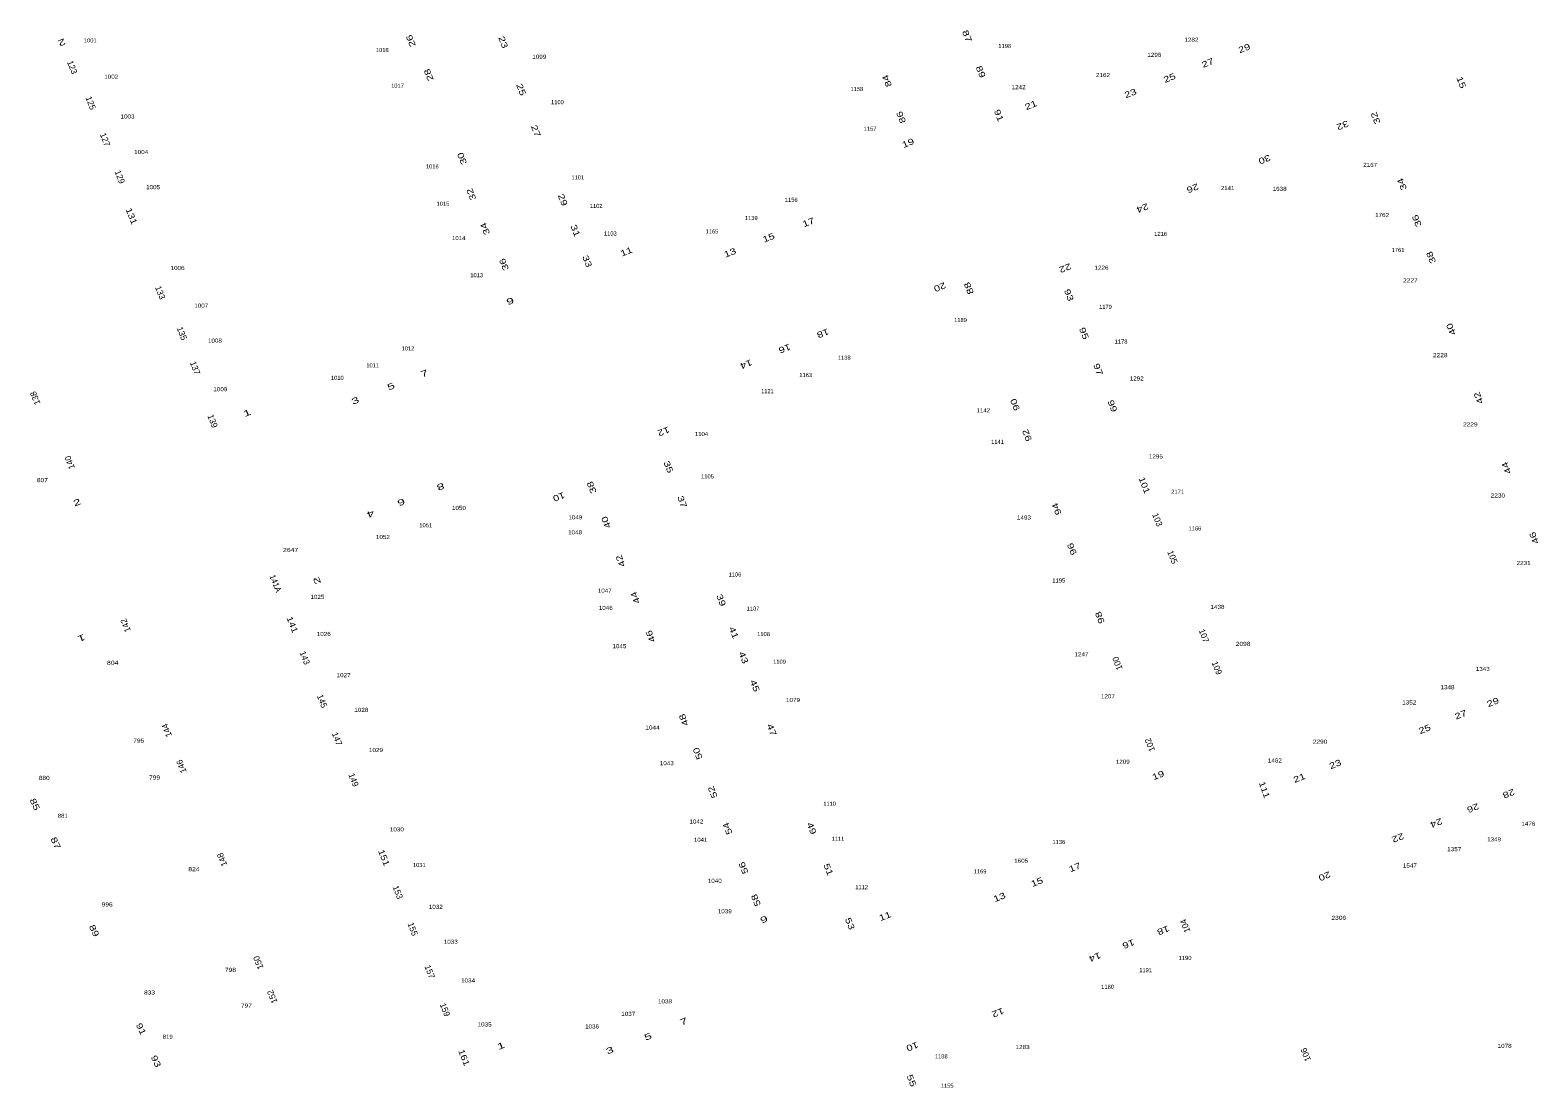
# Model space of a CAD drawing. Extents: x -828673 to -815583, y -1077737 to -1063807.
# Drawn here: x -821441.6 to -821072.8, y -1072104.4 to -1071845.8 of the extents above; entities that cross this region are included whole.
import ezdxf
from ezdxf.enums import TextEntityAlignment as Align

# ---------------------------------------------------------------- set-up
doc = ezdxf.new("R2010")
doc.units = 0
doc.header["$LTSCALE"] = 0.4
doc.layers.add('1', color=7, linetype='Continuous')
doc.layers.add('2', color=7, linetype='Continuous')

msp = doc.modelspace()

# ---------------------------------------------------------------- texts
at = {"layer": '1'}
for s, width, p in [('1001', 1.05, (-821426.855, -1071848.838)), ('1018', 1.05, (-821355.448, -1071851.177)), ('1198', 1.05, (-821203.208, -1071850.196)), ('1282', 1.15, (-821157.545, -1071848.648)), ('1099', 1.15, (-821317.042, -1071852.844)), ('1296', 1.15, (-821166.627, -1071852.363)), ('1002', 1.15, (-821421.722, -1071857.701)), ('2162', 1.15, (-821179.183, -1071857.314)), ('1017', 1.05, (-821351.728, -1071859.925)), ('1158', 1.05, (-821239.376, -1071860.714)), ('1242', 1.15, (-821199.808, -1071860.268)), ('1100', 1.05, (-821312.602, -1071863.939)), ('1003', 1.15, (-821417.748, -1071867.433)), ('1157', 1.05, (-821236.132, -1071870.425)), ('1004', 1.15, (-821414.395, -1071876.13)), ('1016', 1.05, (-821343.2, -1071879.639)), ('2167', 1.15, (-821113.836, -1071879.273)), ('1005', 1.15, (-821411.5, -1071884.718)), ('1156', 1.05, (-821255.43, -1071887.812)), ('2141', 1.1, (-821148.692, -1071884.94)), ('1638', 1.15, (-821135.975, -1071885.124)), ('1015', 1.05, (-821340.598, -1071888.764)), ('1102', 1.05, (-821303.131, -1071889.296)), ('1762', 1.15, (-821110.933, -1071891.535)), ('1165', 1.05, (-821274.809, -1071895.536)), ('1139', 1.05, (-821265.198, -1071892.245)), ('1014', 1.1, (-821336.749, -1071897.171)), ('1103', 1.05, (-821299.671, -1071896.049)), ('1216', 1.05, (-821165.095, -1071896.142)), ('1761', 1.05, (-821107.016, -1071900.063)), ('1006', 1.15, (-821405.508, -1071904.477)), ('1013', 1.05, (-821332.361, -1071906.239)), ('1226', 1.15, (-821179.548, -1071904.408)), ('2227', 1.2, (-821103.984, -1071907.495)), ('1007', 1.15, (-821399.713, -1071913.671)), ('1179', 1.05, (-821178.581, -1071913.983)), ('1189', 1.05, (-821214.032, -1071917.207)), ('1008', 1.15, (-821396.369, -1071922.226)), ('1012', 1.05, (-821349.164, -1071924.144)), ('1178', 1.05, (-821174.757, -1071922.465)), ('1138', 1.05, (-821242.466, -1071926.4)), ('2228', 1.2, (-821096.704, -1071925.796)), ('1010', 1.05, (-821366.44, -1071931.337)), ('1163', 1.05, (-821251.869, -1071930.649)), ('1292', 1.15, (-821170.932, -1071931.5)), ('1009', 1.15, (-821395.044, -1071934.112)), ('1142', 1.1, (-821208.442, -1071939.285)), ('2229', 1.2, (-821089.341, -1071942.722)), ('1104', 1.1, (-821277.375, -1071945.06)), ('1295', 1.15, (-821166.236, -1071950.549)), ('807', 1.2, (-821438.554, -1071956.347)), ('1105', 1.05, (-821275.916, -1071955.437)), ('2171', 1.05, (-821160.938, -1071959.169)), ('2230', 1.2, (-821082.614, -1071960.101)), ('1050', 1.15, (-821336.695, -1071963.133)), ('1049', 1.15, (-821308.221, -1071965.424)), ('1493', 1.15, (-821198.51, -1071965.495)), ('1051', 1.05, (-821344.808, -1071967.378)), ('1048', 1.15, (-821308.299, -1071969.09)), ('1166', 1.05, (-821156.699, -1071968.158)), ('1052', 1.15, (-821355.291, -1071970.25)), ('2647', 1.25, (-821377.862, -1071973.433)), ('2231', 1.15, (-821076.307, -1071976.618)), ('1106', 1.05, (-821269.183, -1071979.421)), ('1047', 1.15, (-821301.031, -1071983.375)), ('1195', 1.05, (-821189.997, -1071980.891)), ('1025', 1.15, (-821371.31, -1071984.893)), ('1046', 1.15, (-821300.782, -1071987.579)), ('1107', 1.05, (-821264.765, -1071987.747)), ('1438', 1.15, (-821151.179, -1071987.34)), ('1026', 1.15, (-821369.749, -1071993.951)), ('1108', 1.05, (-821262.201, -1071993.981)), ('1045', 1.15, (-821297.454, -1071996.943)), ('1247', 1.15, (-821184.436, -1071998.922)), ('2098', 1.2, (-821144.913, -1071996.375)), ('804', 1.25, (-821421.362, -1072001.001)), ('1109', 1.05, (-821258.297, -1072000.728)), ('1343', 1.15, (-821086.3, -1072002.502)), ('1027', 1.15, (-821364.891, -1072004.029)), ('1207', 1.15, (-821177.976, -1072009.186)), ('1348', 1.15, (-821094.916, -1072006.973)), ('1028', 1.15, (-821360.564, -1072012.519)), ('1079', 1.15, (-821254.991, -1072010.09)), ('1352', 1.15, (-821104.269, -1072010.707)), ('1044', 1.2, (-821289.353, -1072016.842)), ('795', 1.2, (-821415.002, -1072020.029)), ('2290', 1.2, (-821126.092, -1072020.284)), ('1029', 1.15, (-821356.986, -1072022.342)), ('1043', 1.15, (-821285.858, -1072025.541)), ('1209', 1.15, (-821174.348, -1072025.205)), ('1462', 1.15, (-821137.15, -1072024.894)), ('880', 1.2, (-821438.114, -1072029.147)), ('799', 1.2, (-821411.121, -1072029.06)), ('881', 1.1, (-821433.579, -1072038.397)), ('1030', 1.15, (-821351.878, -1072041.738)), ('1042', 1.15, (-821278.619, -1072039.816)), ('1476', 1.15, (-821075.162, -1072040.36)), ('1041', 1.1, (-821277.584, -1072044.274)), ('1111', 0.9, (-821244, -1072044.024)), ('1136', 1.05, (-821189.994, -1072044.815)), ('1357', 1.15, (-821093.279, -1072046.576)), ('1349', 1.15, (-821083.539, -1072044.17)), ('1031', 1.05, (-821346.387, -1072050.436)), ('1605', 1.15, (-821199.183, -1072049.392)), ('824', 1.25, (-821401.491, -1072051.458)), ('1169', 1.05, (-821209.239, -1072051.996)), ('1547', 1.15, (-821104.125, -1072050.57)), ('1040', 1.15, (-821274.131, -1072054.305)), ('996', 1.2, (-821422.728, -1072060.096)), ('1032', 1.15, (-821342.351, -1072060.675)), ('1039', 1.15, (-821271.677, -1072061.755)), ('2306', 1.2, (-821121.52, -1072063.362)), ('1033', 1.15, (-821338.691, -1072069.207)), ('798', 1.2, (-821392.557, -1072076.079)), ('1190', 1.05, (-821159.105, -1072073.164)), ('1034', 1.15, (-821334.466, -1072078.662)), ('833', 1.2, (-821412.355, -1072081.62)), ('1180', 1.05, (-821178.056, -1072080.233)), ('797', 1.2, (-821388.676, -1072084.848)), ('1037', 1.15, (-821295.281, -1072086.847)), ('1038', 1.15, (-821286.3, -1072083.77)), ('1035', 1.15, (-821330.406, -1072089.432)), ('1036', 1.15, (-821304.139, -1072089.925)), ('819', 1.1, (-821407.907, -1072092.44)), ('1078', 1.15, (-821080.947, -1072094.671)), ('1188', 1.05, (-821218.736, -1072097.216)), ('1283', 1.15, (-821198.834, -1072094.948)), ('1155', 1.05, (-821217.284, -1072104.417))]:
    msp.add_text(s, height=1, dxfattribs=dict(at, width=width)).set_placement(p, align=Align.CENTER)
for s, p in [('1101', (-821307.609, -1071882.334)), ('1011', (-821357.789, -1071928.273)), ('1121', (-821261.254, -1071934.595)), ('1141', (-821204.978, -1071946.991)), ('1110', (-821246.042, -1072035.47)), ('1112', (-821238.203, -1072055.86)), ('1191', (-821168.746, -1072076.17))]:
    msp.add_text(s, height=1, dxfattribs=at).set_placement(p, align=Align.CENTER)
at = {"layer": '2'}
for s, rotation, width, p in [('87', 291.612, 1.35, (-821213.1119, -1071847.5658)), ('2', 201.854, 1.65, (-821434.0593, -1071848.1341)), ('26', 111.307, 1.35, (-821347.7676, -1071848.1805)), ('23', 291.4, 1.35, (-821326.5503, -1071849.0453)), ('29', 21.878, 1.35, (-821144.3525, -1071850.9592)), ('27', 21.908, 1.35, (-821153.2858, -1071854.5225)), ('28', 111.366, 1.35, (-821343.3849, -1071856.5152)), ('84', 111.699, 1.35, (-821231.3212, -1071857.9743)), ('89', 291.69, 1.35, (-821209.77, -1071856.2768)), ('25', 21.865, 1.35, (-821162.6348, -1071858.1937)), ('15', 291.488, 1.35, (-821092.251, -1071858.8678)), ('25', 291.631, 1.35, (-821322.1484, -1071860.6285)), ('23', 21.315, 1.35, (-821172.2096, -1071861.9563)), ('21', 21.878, 1.35, (-821196.5365, -1071864.8572)), ('86', 111.334, 1.35, (-821227.861, -1071866.8724)), ('91', 291.552, 1.35, (-821205.3375, -1071866.943)), ('32', 201.845, 1.35, (-821120.8469, -1071868.415)), ('32', 111.531, 1.35, (-821111.8282, -1071867.0482)), ('27', 291.657, 1.35, (-821318.5638, -1071870.7392)), ('19', 21.763, 1.35, (-821226.5776, -1071874.1151)), ('30', 111.53, 1.35, (-821335.2402, -1071876.9522)), ('30', 201.754, 1.35, (-821139.9455, -1071876.7557)), ('26', 201.801, 1.35, (-821157.524, -1071883.7998)), ('34', 111.633, 1.35, (-821105.3786, -1071883.2295)), ('32', 111.778, 1.35, (-821332.9712, -1071885.7028)), ('29', 291.829, 1.35, (-821311.9884, -1071887.5971)), ('131', 291.645, 1.25, (-821417.4698, -1071891.5749)), ('24', 201.251, 1.35, (-821169.7807, -1071888.638)), ('36', 111.567, 1.35, (-821101.7389, -1071892.1722)), ('34', 111.848, 1.35, (-821329.6191, -1071894.1101)), ('31', 291.488, 1.35, (-821308.899, -1071895.1208)), ('17', 21.485, 1.35, (-821250.9452, -1071893.5011)), ('15', 21.571, 1.35, (-821260.6842, -1071897.263)), ('36', 111.506, 1.35, (-821324.9804, -1071902.8485)), ('33', 291.674, 1.35, (-821306.0084, -1071902.616)), ('11', 21.48, 1.35, (-821295.4761, -1071900.6742)), ('13', 21.501, 1.35, (-821270.1244, -1071900.9377)), ('38', 111.807, 1.35, (-821098.2459, -1071901.1261)), ('22', 201.151, 1.35, (-821188.7014, -1071903.3115)), ('20', 201.294, 1.35, (-821219.3451, -1071907.963)), ('88', 112.213, 1.35, (-821211.3021, -1071908.6645)), ('93', 291.259, 1.35, (-821188.2008, -1071910.8476)), ('9', 19.822, 1.65, (-821323.9123, -1071912.7973)), ('18', 201.492, 1.35, (-821247.9327, -1071919.2571)), ('95', 291.746, 1.35, (-821184.5125, -1071920.2386)), ('40', 112.82, 1.35, (-821093.3572, -1071918.6659)), ('16', 201.364, 1.35, (-821257.2968, -1071922.9929)), ('14', 201.737, 1.35, (-821266.7217, -1071926.8243)), ('97', 291.522, 1.35, (-821181.0582, -1071929.0414)), ('7', 20.452, 1.65, (-821344.8966, -1071930.4492)), ('5', 21.756, 1.65, (-821353.0265, -1071933.6146)), ('42', 111.621, 1.35, (-821086.6333, -1071935.4983)), ('1', 22.65, 1.65, (-821388.2288, -1071940.0956)), ('3', 22.629, 1.65, (-821361.7636, -1071937.0868)), ('90', 111.497, 1.35, (-821199.9882, -1071937.1283)), ('99', 291.476, 1.35, (-821177.5553, -1071937.9869)), ('12', 201.588, 1.35, (-821286.9051, -1071943.2446)), ('92', 111.524, 1.35, (-821197.0688, -1071944.6247)), ('35', 291.718, 1.35, (-821286.1342, -1071952.88)), ('44', 111.702, 1.35, (-821079.8152, -1071952.6023)), ('8', 201.233, 1.65, (-821341.4389, -1071956.7601)), ('38', 111.603, 1.35, (-821303.5499, -1071957.3571)), ('101', 291.411, 1.25, (-821169.7398, -1071957.3527)), ('2', 21.486, 1.65, (-821429.8252, -1071961.9808)), ('6', 201.219, 1.65, (-821351.0891, -1071960.547)), ('10', 201.497, 1.35, (-821312.5057, -1071959.2522)), ('37', 291.416, 1.35, (-821282.7837, -1071961.4026)), ('4', 201.216, 1.65, (-821358.5771, -1071963.4189)), ('40', 111.642, 1.35, (-821300.0048, -1071965.9116)), ('94', 111.664, 1.35, (-821189.8193, -1071962.6299)), ('96', 111.728, 1.35, (-821186.0791, -1071972.4221)), ('46', 111.633, 1.35, (-821073.0486, -1071969.7175)), ('42', 111.498, 1.35, (-821296.4753, -1071975.3294)), ('141A', 292.085, 0.95, (-821382.2293, -1071981.382)), ('2', 111.686, 1.65, (-821370.7083, -1071980.1451)), ('44', 111.44, 1.35, (-821292.8559, -1071984.3196)), ('39', 291.269, 1.35, (-821273.2515, -1071985.4704)), ('141', 292.087, 1.25, (-821378.1256, -1071991.4505)), ('98', 111.548, 1.35, (-821179.2544, -1071989.191)), ('1', 201.51, 1.65, (-821429.2535, -1071993.7545)), ('46', 111.801, 1.35, (-821289.1138, -1071993.768)), ('41', 291.801, 1.35, (-821270.1652, -1071993.416)), ('43', 291.55, 1.35, (-821267.7775, -1071999.494)), ('45', 291.86, 1.35, (-821265.0156, -1072006.3957)), ('27', 21.444, 1.35, (-821091.4282, -1072013.8772)), ('29', 21.439, 1.35, (-821083.5496, -1072010.8351)), ('48', 111.657, 1.35, (-821281.0112, -1072014.2088)), ('47', 291.439, 1.35, (-821260.8821, -1072017.1784)), ('25', 21.827, 1.35, (-821100.2289, -1072017.4244)), ('50', 111.919, 1.35, (-821277.6007, -1072022.407)), ('19', 21.422, 1.35, (-821165.4094, -1072028.7175)), ('23', 22.019, 1.35, (-821122.0987, -1072025.9877)), ('52', 111.78, 1.35, (-821273.9403, -1072031.8558)), ('111', 289.354, 1.25, (-821140.4079, -1072031.805)), ('21', 21.267, 1.35, (-821130.8915, -1072029.3566)), ('85', 295.286, 1.35, (-821441.0875, -1072035.4276)), ('28', 201.517, 1.35, (-821080.2334, -1072031.8017)), ('24', 201.589, 1.35, (-821097.95, -1072038.9806)), ('26', 201.578, 1.35, (-821088.9707, -1072035.3321)), ('54', 111.759, 1.35, (-821270.3256, -1072040.766)), ('49', 291.516, 1.35, (-821251.1453, -1072041.2544)), ('22', 201.488, 1.35, (-821107.3138, -1072042.613)), ('87', 295.396, 1.35, (-821435.9839, -1072044.8943)), ('151', 291.409, 1.25, (-821355.7269, -1072048.4367)), ('56', 111.812, 1.35, (-821266.414, -1072050.3802)), ('17', 21.516, 1.35, (-821185.7886, -1072051.2073)), ('51', 291.493, 1.35, (-821247.0289, -1072051.3157)), ('15', 21.438, 1.35, (-821195.0556, -1072054.7982)), ('20', 202.416, 1.35, (-821125.269, -1072052.0003)), ('13', 21.601, 1.35, (-821204.2451, -1072058.5051)), ('58', 111.727, 1.35, (-821263.377, -1072058.2871)), ('9', 21.959, 1.65, (-821261.8185, -1072063.9594)), ('53', 291.815, 1.35, (-821241.7649, -1072064.5648)), ('11', 21.196, 1.35, (-821232.2227, -1072063.1512)), ('89', 295.364, 1.35, (-821426.5737, -1072066.3337)), ('18', 201.598, 1.35, (-821164.7209, -1072065.2358)), ('14', 202.024, 1.35, (-821181.4262, -1072071.7794)), ('16', 201.47, 1.35, (-821173.2055, -1072068.5704)), ('12', 201.991, 1.35, (-821205.1422, -1072085.3384)), ('91', 295.482, 1.35, (-821415.0876, -1072090.3548)), ('7', 21.684, 1.65, (-821281.4561, -1072088.8977)), ('1', 21.404, 1.65, (-821326.1487, -1072094.8501)), ('5', 21.05, 1.65, (-821290.1899, -1072092.5956)), ('10', 201.882, 1.35, (-821226.0685, -1072093.6489)), ('93', 295.125, 1.35, (-821411.4486, -1072098.2401)), ('161', 291.58, 1.25, (-821336.137, -1072097.2926)), ('3', 21.374, 1.65, (-821299.5348, -1072095.9577)), ('55', 291.564, 1.35, (-821226.6902, -1072102.9278))]:
    msp.add_text(s, height=1.5, rotation=rotation, dxfattribs=dict(at, width=width)).set_placement(p, align=Align.CENTER)
for s, rotation, p in [('123', 291.843, (-821431.9471, -1071855.174)), ('125', 291.419, (-821427.4347, -1071863.9131)), ('127', 291.565, (-821423.9159, -1071872.8578)), ('129', 291.534, (-821420.3175, -1071881.9857)), ('133', 291.409, (-821410.4337, -1071910.2747)), ('135', 291.577, (-821405.1343, -1071920.2557)), ('137', 291.655, (-821401.9059, -1071928.7042)), ('138', 111.306, (-821439.6283, -1071935.5285)), ('139', 291.699, (-821397.6118, -1071941.6907)), ('140', 110.894, (-821431.1776, -1071951.2715)), ('103', 291.614, (-821166.5583, -1071965.8077)), ('105', 291.833, (-821162.8723, -1071974.9351)), ('142', 111.592, (-821417.5241, -1071991.098)), ('107', 291.653, (-821155.1875, -1071994.1618)), ('143', 291.471, (-821375.0735, -1071999.57)), ('100', 111.017, (-821174.94, -1072000.387)), ('109', 292.049, (-821152.0072, -1072002.0449)), ('145', 291.701, (-821370.839, -1072010.1477)), ('144', 111.658, (-821407.4579, -1072016.7568)), ('147', 291.77, (-821367.1791, -1072019.3868)), ('102', 111.441, (-821167.0127, -1072020.3117)), ('146', 111.669, (-821403.8822, -1072025.5699)), ('149', 291.538, (-821363.1424, -1072029.4167)), ('148', 112.006, (-821393.9046, -1072048.3605)), ('153', 291.598, (-821352.3358, -1072056.8869)), ('155', 291.58, (-821348.6743, -1072065.8772)), ('104', 111.516, (-821158.3778, -1072064.5756)), ('150', 111.801, (-821385.0568, -1072073.5475)), ('157', 291.77, (-821344.5211, -1072076.2928)), ('152', 111.837, (-821381.6548, -1072081.881)), ('159', 291.542, (-821340.8013, -1072085.6156)), ('106', 111.524, (-821128.898, -1072096.0427))]:
    msp.add_text(s, height=1.5, rotation=rotation, dxfattribs=at).set_placement(p, align=Align.CENTER)

doc.saveas('drawing.dxf')
